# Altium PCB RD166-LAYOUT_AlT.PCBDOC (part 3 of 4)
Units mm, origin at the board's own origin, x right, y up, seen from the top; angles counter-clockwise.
Board outline 88.7 x 59.07 mm, 2 copper layers (TOP, BOTTOM), stack 0 mm thick; 138 components, 120 nets, 706 pads, 0 vias.
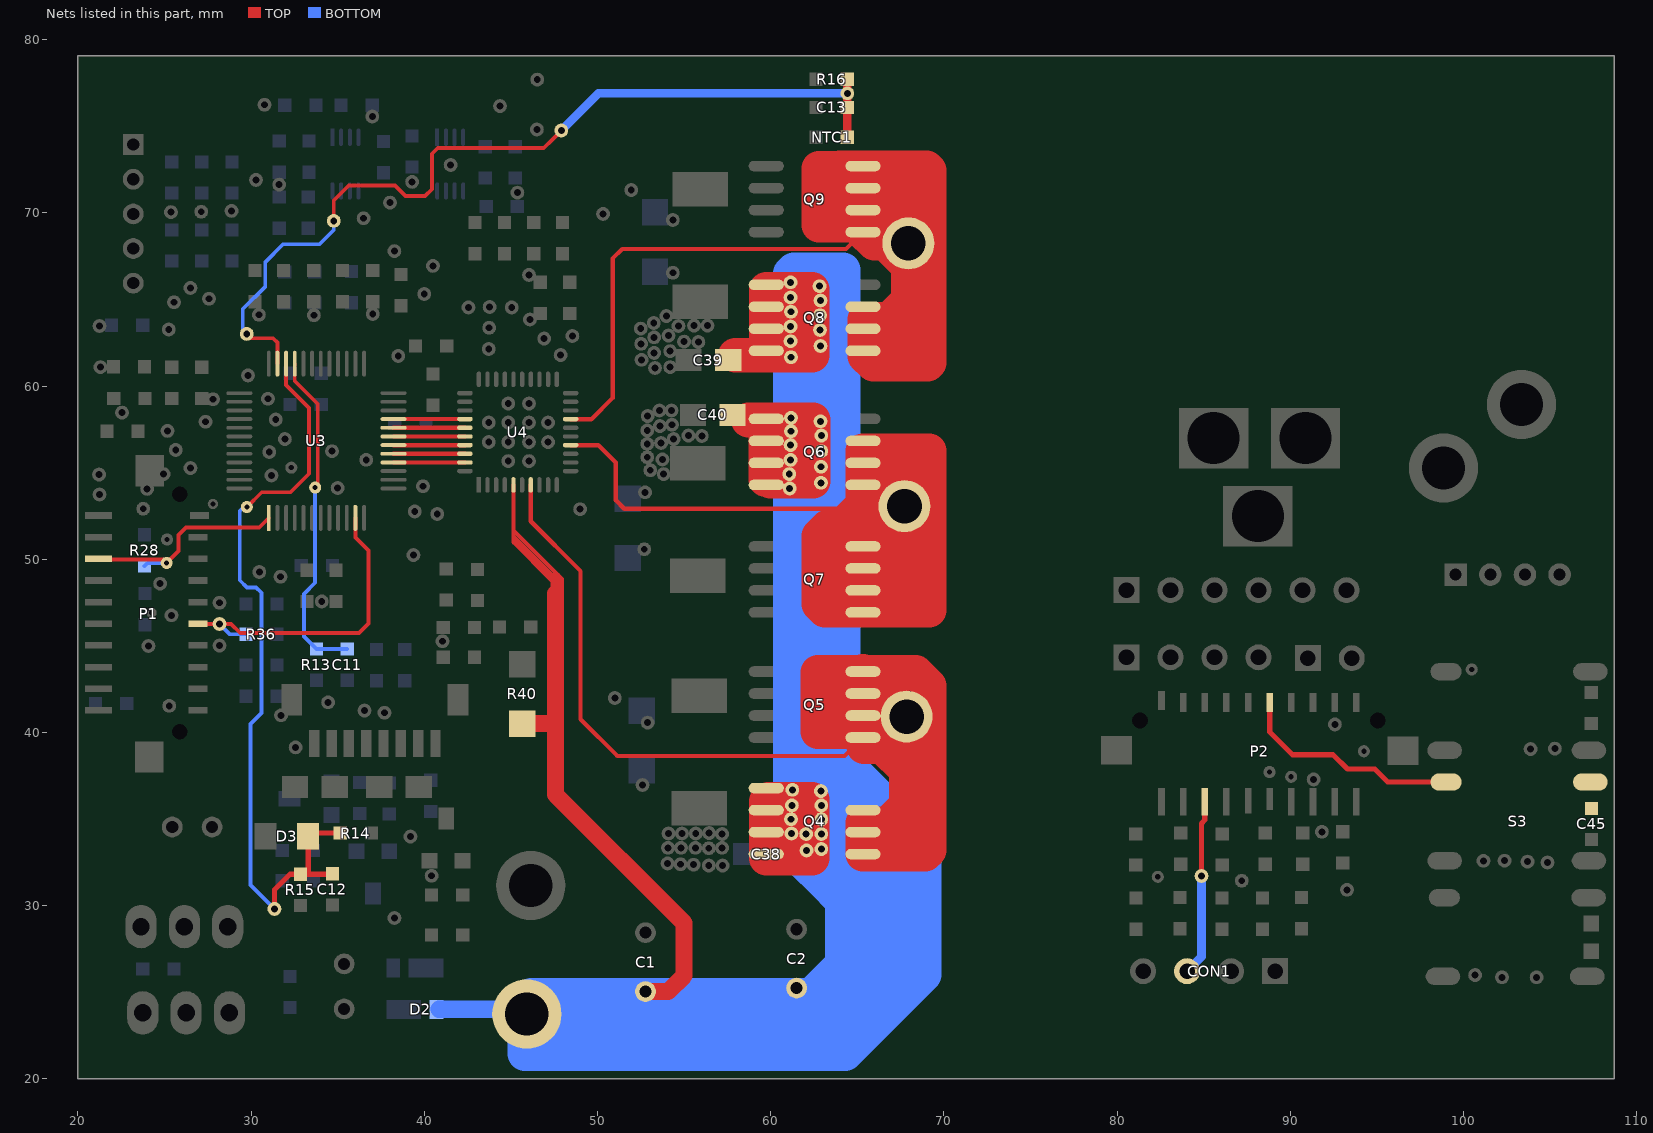
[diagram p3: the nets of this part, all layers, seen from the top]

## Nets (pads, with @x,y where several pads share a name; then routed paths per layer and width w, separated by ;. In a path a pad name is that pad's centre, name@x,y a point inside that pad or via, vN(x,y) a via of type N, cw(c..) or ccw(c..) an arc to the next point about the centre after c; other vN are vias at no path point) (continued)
TMOS: C13.1 NTC1.2 pad.@29.75,63.016 pad.@34.775,69.541 pad.@47.912,74.753 pad.@64.425,76.903 R16.2 U3.35 | length 51.7
  TOP w0.22: pad.@29.75,63.016 30.001,62.765 31.276,62.765 31.526,62.515 U3.35@31.526,61.292 ; pad.@34.776,69.542 34.776,70.715 35.645,71.584 38.307,71.584 38.926,70.965 40.051,70.965 40.451,71.365 40.451,73.415 40.776,73.74 46.901,73.74 47.402,74.241 47.402,74.242 pad.@47.912,74.753
  TOP w0.5: NTC1.2@64.425,74.366 64.425,75.331 64.426,75.332 ; 64.425,75.333 C13.1@64.425,76.091 pad.@64.425,76.903 R16.2@64.425,77.716
  BOTTOM w0.22: pad.@29.75,63.016 29.525,63.241 29.525,64.441 30.825,65.741 30.825,67.166 31.85,68.191 33.95,68.191 34.775,69.016 pad.@34.775,69.541
  BOTTOM w0.5: pad.@47.912,74.753 50.063,76.903 pad.@64.425,76.903
TXD: P1.8 pad.@25.126,49.79 R28.2 U3.1 | length 12.9
  TOP w0.22: P1.8@21.187,50.026 21.223,49.99 24.926,49.99 pad.@25.126,49.79 25.811,50.475 25.811,51.4 26.251,51.84 30.476,51.84 30.689,52.054 30.689,52.055 U3.1@31.025,52.391
  BOTTOM w0.22: R28.2@23.85,49.616 24.024,49.79 pad.@25.126,49.79
TXD1: CON1.3 P2.8 pad.@84.875,31.716 | length 10.2
  TOP w0.3: pad.@84.875,31.716 84.875,32.393 ; 84.876,32.394 84.876,34.749 85.065,34.938 P2.8@85.065,36.003
  BOTTOM w0.5: CON1.3@84.045,26.216 84.875,27.046 pad.@84.875,31.716
U: pad.@67.85,40.916 Q4.1 Q4.2 Q4.3 Q5.5 Q5.6 Q5.7 Q5.8 U4.7 | length 88.3
  TOP w0.25: U4.7@46.151,54.29 46.151,52.19 49.026,49.315 49.026,40.765 51.151,38.64 64.264,38.64 Q5.5@65.331,39.709
  TOP w2: Q5.5@65.332,39.709 Q5.5@65.376,39.709 ; Q5.6@65.332,40.979 Q5.6@65.376,40.979 ; Q5.7@65.332,42.249 Q5.7@65.376,42.249 ; Q5.8@65.332,43.519 Q5.8@65.332,43.474 ; pad.@67.851,40.915 67.826,40.89 67.826,37.815 ; 63.976,43.474 Q5.8@65.332,43.474 ; 63.976,43.474 63.976,40.958 64.643,40.291 64.885,40.049 ; 63.976,43.474 62.735,43.474 62.735,40.049 64.885,40.049 ; 64.885,40.049 64.938,40.102 65.376,40.54 ; Q5.8@65.332,43.474 Q5.8@65.376,43.474 ; Q5.5@65.376,39.709 65.376,39.19 66.451,39.19 ; Q5.5@65.376,39.709 65.376,40.54 ; 65.376,40.54 Q5.6@65.376,40.979 ; Q5.6@65.376,40.979 Q5.7@65.376,42.249 ; Q5.7@65.376,42.249 Q5.8@65.376,43.474 ; Q5.8@65.376,43.474 67.026,43.474 ; 66.451,39.19 67.826,37.815 ; 66.451,39.19 67.026,39.765 67.026,43.474 ; 67.026,43.474 68.367,43.474 69.147,42.694 69.147,35.061 ; 67.826,37.815 67.826,35.79 66.776,34.74 65.363,34.74 65.332,34.771 Q4.2@65.331,34.248 Q4.1@65.331,32.978 68.934,32.977 69.147,33.19 69.147,34.186 ; 69.147,34.186 68.088,33.127 68.088,34.002 69.147,35.061 ; 69.147,34.186 69.147,35.061
U0: U3.21 U4.34 | length 4.1
  TOP w0.22: U3.21@38.225,58.091 41.662,58.09 ; 41.663,58.091 U4.34@42.35,58.091
U2-11: P1.15 pad.@28.18,46.265 R36.1 U3.11 | length 18.5
  TOP w0.22: P1.15@26.925,46.276 26.936,46.265 pad.@28.18,46.265 28.851,46.265 29.376,45.74 36.226,45.74 36.776,46.29 36.776,50.515 36.026,51.265 U3.11@36.025,52.391
  BOTTOM w0.22: pad.@28.18,46.265 28.78,45.666 R36.1@29.7,45.666
U2-11A: C45.1 P2.15 S3.1 S3.4 | length 13.1
  TOP w0.3: P2.15@88.815,41.741 88.815,40.026 90.126,38.715 92.476,38.715 93.301,37.89 94.876,37.89 95.631,37.135 S3.1@98.996,37.135
V: pad.@67.725,53.066 Q6.1 Q6.2 Q6.3 Q7.5 Q7.6 Q7.7 Q7.8 U4.14 | length 69
  TOP w0.25: U4.14@48.45,56.591 50.051,56.59 51.051,55.59 51.051,53.415 51.551,52.915 64.151,52.915 64.626,52.44 65.326,51.74
  TOP w2: 64.151,50.565 64.151,47.065 ; Q7.6@65.331,48.201 Q7.6@65.326,48.201 ; Q7.7@65.331,49.471 Q7.7@65.326,49.471 ; Q7.8@65.331,50.741 Q7.8@65.326,50.741 ; Q6.1@65.331,54.291 Q6.1@65.326,54.291 ; Q6.2@65.331,55.561 Q6.2@65.326,55.561 ; 67.276,55.965 67.276,54.291 pad.@67.276,53.065 ; pad.@67.726,53.065 pad.@67.276,53.065 ; 64.151,47.065 Q7.5@65.326,47.065 ; 64.151,47.065 63.126,47.065 62.776,47.415 62.776,51.34 63.301,51.865 64.051,51.865 64.129,51.943 64.626,52.44 65.326,53.14 ; Q7.5@65.326,47.065 67.276,47.065 ; Q7.5@65.326,47.065 Q7.6@65.326,48.201 ; Q7.6@65.326,48.201 Q7.7@65.326,49.471 ; Q7.7@65.326,49.471 Q7.8@65.326,50.741 ; Q7.8@65.326,50.741 65.326,51.74 65.326,53.14 ; 65.326,53.14 Q6.1@65.326,54.291 ; Q6.1@65.326,54.291 Q6.2@65.326,55.561 ; Q6.2@65.326,55.561 65.326,56.265 69.147,56.265 69.147,47.065 67.276,47.065 ; 67.276,47.065 67.276,50.741 pad.@67.276,53.065
V0: U3.19 U4.36 | length 4.1
  TOP w0.22: U3.19@38.226,57.09 41.449,57.09 ; 41.45,57.091 U4.36@42.35,57.091
VDC_AD: C12.1 D3.1 pad.@29.758,53.015 pad.@31.351,29.815 R14.1 R15.2 U3.34 | length 45.4
  TOP w0.22: pad.@29.758,53.015 30.614,53.87 32.281,53.87 33.351,54.94 33.351,58.74 32.026,60.065 U3.34@32.026,61.29
  TOP w0.3: pad.@31.351,29.815 31.351,30.915 32.251,31.815 R15.2@32.85,31.816 ; R15.2@32.85,31.816 33.301,31.815 ; C12.1@34.7,31.841 34.674,31.815 33.301,31.815 ; R14.1@35.149,34.19 33.449,34.19 D3.1@33.275,34.016 33.301,33.99 33.301,31.815
  BOTTOM w0.22: pad.@29.758,53.015 29.575,53.016 29.35,52.791 29.35,48.791 29.763,48.379 30.287,48.379 30.6,48.066 30.6,41.116 29.975,40.491 29.975,31.191 pad.@31.351,29.815
VM: C1.1 C2.1 C38.2 C39.1 C40.1 D2.2 pad.@45.925,23.741 pad.@61.1,54.091 pad.@61.2,34.166 pad.@61.15,55.741 pad.@61.15,56.591 pad.@61.15,62.591 pad.@61.15,63.441 pad.@61.15,65.116 pad.@61.15,65.991 pad.@61.25,36.691 pad.@61.075,54.916 pad.@61.175,34.991 pad.@61.175,57.391 pad.@61.175,58.166 pad.@61.175,61.666 pad.@61.175,64.291 pad.@61.225,35.791 pad.@62.05,34.141 pad.@62.9,36.616 pad.@62.9,54.416 pad.@62.9,55.341 pad.@62.075,33.191 pad.@62.85,63.241 pad.@62.85,64.091 pad.@62.825,65.766 pad.@62.875,57.966 pad.@62.875,62.316 pad.@62.875,64.941 pad.@62.925,33.266 pad.@62.925,34.141 pad.@62.925,34.991 pad.@62.925,35.791 pad.@62.925,56.241 pad.@62.925,57.141 Q4.5 Q4.6 Q4.7 Q4.8 Q6.5 Q6.6 Q6.7 Q6.8 Q8.5 Q8.6 Q8.7 Q8.8 R40.2 U4.5 | length 377.2
  TOP w0.25: 45.15,52.491 U4.5@45.15,54.291 ; 45.151,52.49 45.151,51.665 ; 47.363,48.778 45.151,50.99 45.151,51.315 ; 47.401,47.59 47.401,49.065 45.151,51.315 ; 47.551,48.165 47.551,49.265 ; 47.701,47.69 47.701,49.115 ; 47.951,47.415 47.951,48.865 47.701,49.115 ; 45.151,51.315 45.151,51.665 ; 45.151,51.665 47.551,49.265 ; 47.551,49.265 47.701,49.115
  TOP w1: R40.2@45.65,40.515 47.451,40.515 ; 47.576,48.015 47.576,36.415 55.001,28.99 55.001,25.965 54.076,25.04 C1.1@52.776,25.04
  TOP w2: C39.1@57.949,61.78 Q8.8@59.998,61.78 ; 58.701,58.04 62.451,58.04 62.451,57.665 ; Q6.8@59.726,54.59 Q6.7@59.726,55.561 ; Q6.7@59.743,55.561 Q6.7@59.726,55.561 ; Q6.6@59.743,56.831 Q6.6@59.726,56.831 ; Q6.8@59.969,54.515 61.076,54.515 ; pad.@61.014,61.907 pad.@61.014,62.59 ; pad.@61.141,34.991 pad.@61.141,35.79 ; pad.@61.141,36.025 pad.@61.141,35.79 ; pad.@61.15,55.741 pad.@61.076,55.74 ; pad.@61.15,56.591 pad.@61.076,56.59 ; pad.@61.15,62.591 pad.@61.014,62.59 ; pad.@61.151,63.44 pad.@61.014,63.44 ; pad.@61.15,65.116 pad.@61.014,65.115 ; pad.@61.175,34.991 61.141,34.99 61.141,34.248 pad.@61.141,34.165 ; pad.@61.175,57.391 61.173,57.385 61.076,57.19 pad.@61.076,56.59 ; pad.@61.175,64.291 pad.@61.014,64.29 ; pad.@61.201,34.165 pad.@61.141,34.165 ; pad.@61.226,35.79 pad.@61.141,35.79 ; pad.@62.05,34.141 pad.@62.411,34.14 ; pad.@62.075,33.191 pad.@62.411,33.19 ; Q6.7@59.726,55.561 Q6.6@59.726,56.831 ; Q6.6@59.726,56.831 59.726,57.665 62.451,57.665 ; Q8.8@59.998,61.78 62.411,61.78 62.411,63.241 62.411,64.941 62.411,65.583 61.014,65.583 ; Q8.8@59.998,61.78 Q8.8@59.743,62.035 Q8.7@59.743,63.305 59.744,65.583 61.014,65.583 ; pad.@61.014,62.59 61.014,63.305 pad.@61.014,63.44 ; pad.@61.014,63.44 pad.@61.014,64.29 ; pad.@61.014,64.29 pad.@61.014,65.115 ; pad.@61.014,65.115 61.014,65.583 ; 61.076,54.515 62.451,54.515 62.451,56.241 62.451,57.665 ; 61.076,54.515 61.076,55.561 pad.@61.076,55.74 ; pad.@61.076,55.74 pad.@61.076,56.59 ; 61.141,32.74 62.411,32.74 pad.@62.411,33.19 ; 61.141,32.74 61.141,34.141 pad.@61.141,34.165 ; 61.141,32.74 59.744,32.74 59.744,36.025 59.871,36.152 62.411,36.152 62.411,34.166 pad.@62.411,34.14 ; pad.@62.411,33.191 pad.@62.411,34.14
  BOTTOM w1: D2.2@40.852,24.016 pad.@45.375,24.016 ; pad.@45.375,24.016 45.8,23.803 pad.@45.925,23.741 45.8,23.866 45.65,24.016 pad.@45.375,24.016
  BOTTOM w2: pad.@45.925,23.741 pad.@45.8,23.741 ; pad.@61.075,54.916 pad.@61.14,54.916 ; pad.@61.1,54.091 pad.@61.14,54.091 ; 62.202,66.266 62.202,65.991 ; 63.55,39.016 64.188,38.378 ; 64.188,31.379 64.188,33.366 ; pad.@45.8,23.741 45.8,23.803 45.8,23.866 pad.@45.8,24.441 ; pad.@45.8,23.741 45.8,21.466 64.3,21.466 67.7,24.866 ; pad.@45.8,24.441 46.212,24.028 47.3,22.941 63.125,22.941 65.875,25.691 65.875,31.679 64.188,33.366 ; pad.@45.8,24.441 46.175,24.816 62.35,24.816 64.15,26.616 64.15,30.266 62.925,31.491 ; C38.2@61.14,33.366 pad.@62.05,33.366 ; C38.2@61.14,33.366 pad.@61.14,34.166 ; C38.2@61.14,33.366 61.14,33.276 61.162,33.254 61.65,32.766 62.038,32.378 62.925,31.491 ; pad.@61.14,34.166 pad.@61.14,34.991 ; pad.@61.14,34.166 pad.@61.2,34.166 62.075,34.166 pad.@62.202,34.166 ; pad.@61.14,34.991 pad.@61.14,35.791 ; pad.@61.14,34.991 pad.@61.175,34.991 62.202,34.991 ; pad.@61.14,35.791 pad.@61.14,36.691 ; pad.@61.14,35.791 pad.@61.225,35.791 62.202,35.791 ; pad.@61.14,36.691 pad.@61.25,36.691 62.202,36.691 ; pad.@61.14,36.691 pad.@61.14,54.091 ; pad.@61.14,54.091 pad.@61.14,54.916 ; pad.@61.14,54.091 62.202,54.091 ; pad.@61.14,54.916 62.202,54.916 ; pad.@61.14,54.916 pad.@61.14,55.741 ; pad.@61.14,55.741 pad.@61.15,55.741 62.202,55.741 ; pad.@61.14,55.741 pad.@61.14,56.591 ; pad.@61.14,56.591 pad.@61.15,56.591 62.202,56.591 ; pad.@61.14,56.591 pad.@61.14,57.391 ; pad.@61.14,57.391 pad.@61.175,57.391 62.202,57.391 ; pad.@61.14,57.391 pad.@61.14,58.166 ; pad.@61.14,58.166 pad.@61.175,58.166 62.202,58.166 ; pad.@61.14,58.166 pad.@61.14,61.666 ; pad.@61.14,61.666 pad.@61.175,61.666 62.202,61.666 ; pad.@61.14,61.666 pad.@61.14,62.591 ; pad.@61.14,62.591 pad.@61.14,63.441 ; pad.@61.14,62.591 pad.@61.15,62.591 62.202,62.591 ; pad.@61.14,63.441 pad.@61.14,64.291 ; pad.@61.14,63.441 pad.@61.15,63.441 62.202,63.441 ; pad.@61.14,64.291 pad.@61.14,65.116 ; pad.@61.14,64.291 pad.@61.175,64.291 62.202,64.291 ; pad.@61.14,65.116 pad.@61.15,65.116 62.202,65.116 ; pad.@61.14,65.116 pad.@61.14,65.991 ; pad.@61.14,65.991 pad.@61.15,65.991 62.202,65.991 ; pad.@61.14,65.991 61.14,66.516 61.327,66.703 62.825,66.703 ; pad.@62.05,33.366 pad.@62.05,34.141 pad.@62.202,34.141 ; pad.@62.05,33.366 pad.@62.075,33.366 ; pad.@62.075,33.366 pad.@62.678,33.366 ; pad.@62.075,33.366 pad.@62.075,33.191 62.306,33.258 pad.@62.678,33.366 ; pad.@62.202,34.141 pad.@62.925,34.141 pad.@62.925,33.366 ; pad.@62.202,34.141 pad.@62.202,34.166 ; pad.@62.202,34.141 62.202,34.064 62.525,33.741 62.575,33.691 pad.@62.85,33.416 ; pad.@62.202,34.166 62.202,34.991 ; 62.202,34.991 pad.@62.925,34.991 64.188,34.991 ; 62.202,34.991 62.202,35.791 ; 62.202,35.791 pad.@62.925,35.791 64.188,35.791 ; 62.202,35.791 62.202,36.616 ; 62.202,36.616 62.202,36.691 ; 62.202,36.616 pad.@62.9,36.616 64.188,36.616 ; 62.202,36.691 62.202,54.091 ; 62.202,54.091 62.202,54.416 ; 62.202,54.416 62.202,54.916 ; 62.202,54.416 pad.@62.9,54.416 64.188,54.416 ; 62.202,54.916 62.202,55.341 ; 62.202,55.341 pad.@62.9,55.341 64.188,55.341 ; 62.202,55.341 62.202,55.741 ; 62.202,55.741 62.202,56.241 ; 62.202,56.241 pad.@62.925,56.241 64.188,56.241 ; 62.202,56.241 62.202,56.591 ; 62.202,56.591 62.202,57.141 ; 62.202,57.141 pad.@62.925,57.141 64.188,57.141 ; 62.202,57.141 62.202,57.391 ; 62.202,57.391 62.202,57.966 ; 62.202,57.966 62.202,58.166 ; 62.202,57.966 pad.@62.875,57.966 64.188,57.966 ; 62.202,58.166 62.202,61.666 ; 62.202,61.666 62.202,62.316 ; 62.202,62.316 pad.@62.875,62.316 64.188,62.316 ; 62.202,62.316 62.202,62.591 ; 62.202,62.591 62.202,63.241 ; 62.202,63.241 pad.@62.85,63.241 64.188,63.241 ; 62.202,63.241 62.202,63.441 ; 62.202,63.441 62.202,64.091 ; 62.202,64.091 pad.@62.85,64.091 64.188,64.091 ; 62.202,64.091 62.202,64.291 ; 62.202,64.291 62.202,64.941 ; 62.202,64.941 pad.@62.875,64.941 64.188,64.941 ; 62.202,64.941 62.202,65.116 ; 62.202,65.116 62.202,65.766 ; 62.202,65.766 62.202,65.991 ; 62.202,65.766 pad.@62.825,65.766 62.825,66.703 ; pad.@62.678,33.366 pad.@62.875,33.366 ; pad.@62.678,33.366 pad.@62.85,33.416 ; 62.825,66.703 64.188,66.703 64.188,64.941 ; pad.@62.85,33.416 pad.@62.875,33.366 ; pad.@62.875,33.366 pad.@62.925,33.366 ; pad.@62.875,33.366 pad.@62.925,33.266 62.925,31.491 ; pad.@62.925,33.366 64.188,33.366 ; 64.188,33.366 64.188,34.991 ; 64.188,34.991 64.188,35.791 ; 64.188,35.791 64.188,35.953 ; 64.188,35.953 64.188,36.616 ; 64.188,35.953 67.7,32.441 67.7,24.866 ; 64.188,36.616 64.188,38.378 ; 64.188,38.378 64.188,54.416 ; 64.188,38.378 68.85,33.716 68.85,26.016 67.7,24.866 ; 64.188,54.416 64.188,55.341 ; 64.188,55.341 64.188,56.241 ; 64.188,56.241 64.188,57.141 ; 64.188,57.141 64.188,57.966 ; 64.188,57.966 64.188,62.316 ; 64.188,62.316 64.188,63.241 ; 64.188,63.241 64.188,64.091 ; 64.188,64.091 64.188,64.941
VSP: C11.1 pad.@33.701,54.14 R13.2 U3.33 | length 19.4
  TOP w0.22: U3.33@32.525,61.291 32.526,60.29 33.851,58.965 33.851,54.29 pad.@33.701,54.14
  BOTTOM w0.22: pad.@33.701,54.14 33.7,48.641 33.05,47.991 33.05,45.541 R13.2@33.775,44.816 C11.1@35.55,44.816
W: pad.@67.95,68.241 Q8.1 Q8.2 Q8.3 Q9.5 Q9.6 Q9.7 Q9.8 U4.17 | length 92.4
  TOP w0.25: U4.17@48.451,58.09 49.651,58.09 50.876,59.315 50.876,67.365 51.426,67.915 64.355,67.915 Q9.5@65.331,68.893
  TOP w2: 64.001,69.303 64.001,72.577 ; 64.001,69.303 64.921,69.303 Q9.5@65.331,68.893 ; 64.001,69.303 62.789,69.303 62.789,72.577 64.001,72.577 ; 64.001,72.577 64.001,72.59 Q9.8@65.332,72.59 ; Q9.5@65.331,68.893 Q9.6@65.331,70.163 Q9.8@65.332,72.59 ; Q9.5@65.331,68.893 65.984,68.24 pad.@66.626,68.24 ; Q9.8@65.332,72.59 66.751,72.59 ; pad.@66.626,68.24 pad.@67.951,68.24 ; pad.@66.626,68.24 67.288,67.579 pad.@67.951,66.915 ; 66.751,72.59 66.876,72.465 66.876,69.315 pad.@67.951,68.24 ; 66.751,72.59 68.326,72.59 ; 66.851,63.865 65.451,63.865 65.451,61.74 65.926,61.265 66.901,61.265 ; 66.851,63.865 66.901,63.815 66.901,61.265 ; 66.851,63.865 67.951,64.965 pad.@67.951,66.915 ; 66.901,61.265 68.326,61.265 ; pad.@67.951,66.915 pad.@67.951,68.24 ; 68.326,61.265 68.326,72.59 ; 68.326,61.265 69.072,61.265 69.147,61.34 69.147,72.444 69.001,72.59 68.326,72.59
W0: U3.17 U4.38 | length 4.1
  TOP w0.25: U3.17@38.225,56.091 41.622,56.09 ; 41.622,56.091 U4.38@42.35,56.091
X0: U3.20 U4.35 | length 4.1
  TOP w0.25: U3.20@38.226,57.59 41.622,57.59 ; 41.622,57.591 U4.35@42.35,57.591
Y0: U3.18 U4.37 | length 4.1
  TOP w0.25: U3.18@38.225,56.591 41.521,56.59 ; 41.522,56.591 U4.37@42.35,56.591
Z0: U3.16 U4.39 | length 4.1
  TOP w0.25: U3.16@38.225,55.591 U4.39@42.35,55.591
pads on no net: P1.23 P1.24 P2.21 P2.23 P2.24 SW1.6 SW1.9

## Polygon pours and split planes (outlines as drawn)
+5V1 on TOP "TOP171" (solid, pour order 295): 37 vertices, not listed, extent 79.076,25.415 94.651,49.19
19VDC on TOP "TOP169" (solid, pour order 293): 105.301,60.74 105.901,60.14 105.901,57.99 104.776,56.865 102.426,56.865 101.176,58.115 95.801,58.115 92.976,55.29 88.851,55.29 88.851,58.715 90.876,60.74
EMG1 on TOP "TOP131" (solid, pour order 255): 93.946,43.154 cw(c93.801,43.191) 93.695,43.085 93.02,43.761 93.542,44.328 94.119,43.829 93.946,43.154
GND1 on TOP "TOP121" (solid, pour order 245): 98.151,39.64 106.251,39.64 106.526,39.915 106.526,40.84 106.701,41.015 108.026,41.015 108.226,40.815 108.226,38.54 108.126,38.44 97.976,38.44 97.851,38.565 97.851,39.34
GND1 on TOP "TOP120" (solid, pour order 244): 106.676,34.315 108.076,34.315 108.376,34.015 108.376,32.165 108.101,31.89 98.026,31.89 97.726,32.19 97.726,32.765 98.101,33.14 106.301,33.14 106.651,33.49 106.651,34.29
GND1 on TOP "TOP119" (solid, pour order 243): 90.319,33.665 cw(c90.319,33.838) 90.216,33.7 90.201,33.715 90.176,33.74 cw(c90.368,33.841) 90.151,33.841 90.151,34.541 cw(c90.286,34.53) 90.286,34.665 93.387,34.665 cw(c93.386,34.575) 93.476,34.575 93.476,33.811 cw(c93.33,33.811) 93.336,33.665
GND1 on TOP "TOP118" (solid, pour order 242): 27 vertices, not listed, extent 79.176,24.715 98.851,27.065
GND1 on TOP "TOP117" (solid, pour order 241): 108.376,25.69 108.001,25.315 98.051,25.315 97.776,25.59 97.726,25.64 97.726,26.44 97.951,26.665 106.276,26.665 106.751,27.14 106.751,27.765 108.176,27.765 108.376,27.565
GND1 on TOP "TOP116" (solid, pour order 240): 82.245,32.054 cw(c82.351,31.948) 82.457,32.054 ccw(c82.697,32.153) 82.598,31.913 82.351,31.628 82.103,31.913 ccw(c82.004,32.153) 82.245,32.054
GND1 on TOP "TOP115" (solid, pour order 239): 87.051,44.815 84.776,47.09 84.776,49.006 cw(c84.946,48.994) 84.946,49.165 86.476,49.165 86.876,48.765 86.876,47.24 87.576,46.54 88.601,45.515 91.401,45.515 91.801,45.115 91.801,43.615 91.651,43.465 87.526,43.465 87.051,43.94
K-UP1 on TOP "TOP107" (solid, pour order 231): 106.301,31.09 108.226,31.09 108.401,30.915 108.401,28.865 108.101,28.565 106.851,28.565 106.551,28.865 106.551,29.64 106.251,29.94 98.101,29.94 97.851,30.19 97.851,30.815 98.201,31.165
LEDB on TOP "TOP105" (solid, pour order 229): 89.199,33.791 89.049,33.641 87.974,33.641 87.974,33.666 87.674,33.966 87.674,35.1 cw(c87.715,35.095) 87.715,35.136 87.956,35.136 87.956,35.311 cw(c87.992,35.301) 87.992,35.338 88.424,35.338 88.424,35.315 88.575,35.315 89.199,34.691
N172117 on TOP "TOP100" (solid, pour order 224): 91.226,32.84 91.401,32.665 91.401,30.315 91.101,30.015 90.301,30.015 90.226,30.09 90.226,32.84
N29992 on TOP "TOP89" (solid, pour order 213): 84.126,32.74 84.126,30.015 83.226,30.015 83.176,30.065 83.176,32.815 84.051,32.815
N30008 on TOP "TOP88" (solid, pour order 212): 86.526,32.715 86.526,30.065 86.451,29.99 85.676,29.99 85.601,30.065 85.601,32.715
N30012 on TOP "TOP87" (solid, pour order 211): 89.151,32.69 89.151,30.09 89.001,29.94 88.026,29.94 87.951,30.015 87.951,32.84 89.001,32.84
N30064 on TOP "TOP86" (solid, pour order 210): 81.626,32.69 81.626,30.04 81.501,29.915 80.751,29.915 80.576,30.09 80.576,32.661 cw(c80.721,32.644) 80.721,32.79 81.526,32.79
NRESET1 on TOP "TOP63" (solid, pour order 187): 108.426,41.99 108.151,41.715 106.676,41.715 106.551,41.84 106.551,42.865 106.276,43.14 98.101,43.14 97.926,43.315 97.926,43.94 98.126,44.14 108.201,44.14 108.426,43.915
NRESET1 on TOP "TOP62" (solid, pour order 186): 93.9,39.116 cw(c94.05,39.116) 94.05,39.266 94.25,39.266 94.276,38.889 93.9,38.916 93.9,39.116
PGND1 on TOP "TOP46" (solid, pour order 170): 86.251,54.215 93.226,54.215 96.326,57.315 100.426,57.315 101.201,56.54 101.201,53.615 100.051,52.465 97.701,52.465 95.876,50.64 85.976,50.64 85.976,53.94
SCL1 on TOP "TOP42" (solid, pour order 166): 99.642,47.847 cw(c99.551,47.965) 99.459,47.847 ccw(c98.424,47.474) 98.9,48.466 99.55,49.154 100.2,48.466 ccw(c100.677,47.476) 99.642,47.847
SCLK1 on TOP "TOP39" (solid, pour order 163): 88.907,37.326 cw(c88.801,37.432) 88.695,37.326 88.554,37.468 88.801,37.753 89.048,37.468 88.907,37.326
SDA1 on TOP "TOP38" (solid, pour order 162): 92.453,40.929 cw(c92.565,40.83) 92.671,40.936 92.858,40.749 92.576,40.428 92.286,40.743 92.453,40.929
SWCLK1 on TOP "TOP33" (solid, pour order 157): 85.025,43.591 cw(c85.025,43.741) 84.875,43.741 84.875,44.341 85.652,44.368 85.625,43.591 85.025,43.591
SYNC2A on TOP "TOP30" (solid, pour order 154): 91.432,36.806 cw(c91.326,36.912) 91.206,36.822 91.054,37.023 91.353,37.328 91.634,37.008 91.432,36.806
TXD1 on TOP "TOP20" (solid, pour order 144): 84.769,32.176 cw(c84.875,32.07) 84.981,32.176 ccw(c85.282,32.3) 85.158,31.999 84.875,31.678 84.592,31.999 ccw(c84.468,32.3) 84.769,32.176
U2-11A on TOP "TOP16" (solid, pour order 140): 98.036,37.615 108.176,37.615 108.376,37.415 108.376,35.64 107.901,35.165 106.876,35.165 106.601,35.44 106.601,36.015 106.051,36.565 97.926,36.565 97.901,36.59 97.901,37.465 98.026,37.59
+5V on TOP "TOP176" (solid, pour order 300): 32.494,50.118 32.494,49.451 31.928,48.886 31.674,48.886 31.619,48.941 31.619,49.463 32.314,50.157 32.454,50.157
+5V on TOP "TOP175" (solid, pour order 299): 27.501,27.79 27.501,33.726 cw(c27.602,33.725) 27.621,33.825 ccw(c27.75,34.541) 28.477,34.53 28.478,34.58 29.66,34.58 30.07,34.171 30.276,33.965 30.276,33.127 30.276,28.065 29.451,27.24 28.051,27.24
+5V on TOP "TOP174" (solid, pour order 298): 17 vertices, not listed, extent 20.751,33.115 31.426,41.668
+5V on TOP "TOP173" (solid, pour order 297): 29.3,39.614 31.351,41.665 31.351,42.461 cw(c31.441,42.45) 31.441,42.54 32.92,42.54 cw(c32.917,42.457) 33.001,42.457 33.001,40.79 32.876,40.665 31.78,40.665 31.426,40.311 31.026,39.911 31.026,38.915 29.998,38.915
+5V on TOP "TOP172" (solid, pour order 296): 22.976,58.215 22.251,57.49 22.251,57.24 21.976,56.965 21.176,56.965 21.176,59.165 21.701,59.69 22.401,59.69 22.401,59.29 22.976,58.715
12V on TOP "TOP170" (solid, pour order 294): 24.051,22.115 22.626,22.115 21.901,22.84 21.901,29.665 22.276,30.04 24.076,30.04 24.176,29.94 24.226,29.94 24.526,29.64 24.526,22.59
5V on TOP "TOP168" (solid, pour order 292): 27.332,59.032 cw(c27.347,59.094) 27.302,59.139 ccw(c27.152,59.505) 27.517,59.354 27.815,59.246 27.547,58.982 ccw(c27.379,58.749) 27.332,59.032
5V on TOP "TOP167" (solid, pour order 291): 46.245,63.323 cw(c46.151,63.38) 46.073,63.302 ccw(c45.638,63.123) 45.817,63.558 46.097,63.868 46.399,63.579 ccw(c46.629,63.266) 46.245,63.323
5V on TOP "TOP166" (solid, pour order 290): 47.645,64.129 cw(c47.938,64.191) 47.645,64.253 ccw(c47.349,64.98) 48.019,64.572 48.475,64.191 48.019,63.81 ccw(c47.349,63.402) 47.645,64.129
5V on TOP "TOP165" (solid, pour order 289): 47.455,64.253 cw(c47.162,64.191) 47.455,64.129 ccw(c47.751,63.402) 47.081,63.81 46.625,64.191 47.081,64.572 ccw(c47.751,64.98) 47.455,64.253
AGND on TOP "TOP164" (solid, pour order 288): 27.873,61.125 cw(c27.575,61.091) 27.873,61.056 ccw(c28.23,60.362) 27.531,60.71 27.075,61.091 27.531,61.472 ccw(c28.23,61.82) 27.873,61.125
AGND on TOP "TOP163" (solid, pour order 287): 26.394,61.029 cw(c26.688,61.091) 26.394,61.154 ccw(c26.1,61.879) 26.769,61.472 27.225,61.091 26.769,60.71 ccw(c26.099,60.302) 26.394,61.029
AGND on TOP "TOP162" (solid, pour order 286): 26.18,61.153 cw(c25.887,61.091) 26.18,61.029 ccw(c26.476,60.302) 25.806,60.71 25.35,61.091 25.806,61.472 ccw(c26.476,61.88) 26.18,61.153
AGND on TOP "TOP161" (solid, pour order 285): 24.648,61.04 cw(c24.938,61.116) 24.65,61.202 ccw(c24.43,61.944) 25.044,61.472 25.5,61.087 25.044,60.71 ccw(c24.359,60.29) 24.648,61.04
AGND on TOP "TOP160" (solid, pour order 284): 24.605,61.178 cw(c24.312,61.116) 24.605,61.054 ccw(c24.901,60.327) 24.231,60.735 23.775,61.116 24.231,61.497 ccw(c24.901,61.905) 24.605,61.178
AGND on TOP "TOP159" (solid, pour order 283): 30.98,66.728 cw(c30.687,66.666) 30.98,66.603 ccw(c31.276,65.877) 30.606,66.285 30.15,66.666 30.606,67.047 ccw(c31.276,67.455) 30.98,66.728
AGND on TOP "TOP158" (solid, pour order 282): 29.469,66.603 cw(c29.763,66.665) 29.469,66.728 ccw(c29.174,67.455) 29.844,67.047 30.3,66.666 29.844,66.285 ccw(c29.175,65.876) 29.469,66.603
AGND on TOP "TOP157" (solid, pour order 281): 32.63,66.728 cw(c32.337,66.666) 32.63,66.604 ccw(c32.926,65.877) 32.256,66.285 31.8,66.666 32.256,67.047 ccw(c32.926,67.455) 32.63,66.728
AGND on TOP "TOP156" (solid, pour order 280): 31.119,66.603 cw(c31.413,66.666) 31.119,66.728 ccw(c30.824,67.455) 31.494,67.047 31.95,66.666 31.494,66.285 ccw(c30.825,65.877) 31.119,66.603
AGND on TOP "TOP155" (solid, pour order 279): 34.38,66.728 cw(c34.087,66.666) 34.38,66.603 ccw(c34.676,65.877) 34.006,66.285 33.55,66.666 34.006,67.047 ccw(c34.676,67.455) 34.38,66.728
AGND on TOP "TOP154" (solid, pour order 278): 32.869,66.603 cw(c33.163,66.666) 32.869,66.729 ccw(c32.575,67.454) 33.244,67.047 33.7,66.666 33.244,66.285 ccw(c32.574,65.877) 32.869,66.603
AGND on TOP "TOP153" (solid, pour order 277): 36.03,66.728 cw(c35.737,66.666) 36.03,66.604 ccw(c36.326,65.877) 35.656,66.285 35.2,66.666 35.656,67.047 ccw(c36.326,67.455) 36.03,66.728
AGND on TOP "TOP152" (solid, pour order 276): 34.519,66.603 cw(c34.813,66.666) 34.519,66.728 ccw(c34.224,67.455) 34.894,67.047 35.35,66.666 34.894,66.285 ccw(c34.225,65.877) 34.519,66.603
AGND on TOP "TOP151" (solid, pour order 275): 37.748,66.7 cw(c37.45,66.666) 37.748,66.631 ccw(c38.106,65.936) 37.406,66.285 36.95,66.666 37.406,67.047 ccw(c38.106,67.396) 37.748,66.7
AGND on TOP "TOP150" (solid, pour order 274): 36.269,66.603 cw(c36.563,66.666) 36.269,66.729 ccw(c35.975,67.454) 36.644,67.047 37.1,66.666 36.644,66.285 ccw(c35.974,65.877) 36.269,66.603
AGND on TOP "TOP149" (solid, pour order 273): 37.895,66.379 cw(c38.188,66.441) 37.895,66.503 ccw(c37.599,67.23) 38.269,66.822 38.725,66.441 38.269,66.06 ccw(c37.599,65.652) 37.895,66.379
AGND on TOP "TOP148" (solid, pour order 272): 39.405,66.503 cw(c39.112,66.441) 39.405,66.379 ccw(c39.701,65.652) 39.031,66.06 38.575,66.441 39.031,66.822 ccw(c39.701,67.23) 39.405,66.503
AGND on TOP "TOP147" (solid, pour order 271): 47.645,65.928 cw(c47.938,65.991) 47.645,66.053 ccw(c47.349,66.78) 48.019,66.372 48.475,65.991 48.019,65.61 ccw(c47.349,65.202) 47.645,65.928
AGND on TOP "TOP146" (solid, pour order 270): 40.078,64.828 cw(c40,64.906) 39.922,64.828 ccw(c39.573,64.684) 39.717,65.033 40,65.343 40.283,65.033 ccw(c40.427,64.684) 40.078,64.828
AMP_U on TOP "TOP145" (solid, pour order 269): 41.604,72.278 cw(c41.526,72.355) 41.448,72.277 ccw(c41.098,72.133) 41.242,72.483 41.525,72.793 41.808,72.483 ccw(c41.953,72.135) 41.604,72.278
AMP_U on TOP "TOP144" (solid, pour order 268): 40.79,67.341 cw(c40.79,67.231) 40.9,67.231 ccw(c41.247,67.086) 40.9,66.941 40.481,66.921 40.5,67.341 ccw(c40.645,67.688) 40.79,67.341
AMP_U on TOP "TOP143" (solid, pour order 267): 47.004,62.263 cw(c46.926,62.34) 46.848,62.262 ccw(c46.515,62.126) 46.652,62.458 46.925,62.769 47.198,62.459 ccw(c47.336,62.128) 47.004,62.263
AMP_V on TOP "TOP142" (solid, pour order 266): 47.261,61.5 47.551,61.79 47.901,61.802 47.876,61.39 ccw(c47.568,60.653) 47.261,61.39
AMP_V on TOP "TOP141" (solid, pour order 265): 38.198,69.852 ccw(c37.423,69.533) 37.742,70.308 38.015,70.617 38.276,70.34 38.276,69.93
AMP_V on TOP "TOP140" (solid, pour order 264): 38.198,68.28 cw(c38.276,68.202) 38.354,68.279 ccw(c38.703,68.422) 38.558,68.073 38.275,67.763 37.992,68.074 ccw(c37.848,68.424) 38.198,68.28
AMP_W on TOP "TOP139" (solid, pour order 263): 48.783,62.329 cw(c48.676,62.355) 48.598,62.278 ccw(c48.037,62.047) 48.268,62.608 48.545,62.917 48.863,62.659 ccw(c49.218,62.398) 48.783,62.329
CAL on TOP "TOP138" (solid, pour order 262): 38.969,62.293 cw(c39.077,62.316) 38.969,62.339 ccw(c38.805,62.632) 39.119,62.514 39.528,62.316 39.119,62.118 ccw(c38.805,62) 38.969,62.293
CAL on TOP "TOP137" (solid, pour order 261): 38.792,62.141 cw(c38.792,62.031) 38.902,62.03 ccw(c39.248,61.883) 38.9,61.74 38.48,61.722 38.5,62.141 ccw(c38.646,62.491) 38.792,62.141
CAL on TOP "TOP136" (solid, pour order 260): 29.535,60.216 cw(c29.535,60.326) 29.425,60.326 ccw(c29.078,60.471) 29.425,60.616 29.844,60.635 29.825,60.216 ccw(c29.68,59.869) 29.535,60.216
DIN on TOP "TOP135" (solid, pour order 259): 25.489,46.288 cw(c25.401,46.376) 25.312,46.288 25.118,46.482 25.401,46.796 25.683,46.482 25.489,46.288
EMG on TOP "TOP134" (solid, pour order 258): 40.46,52.216 cw(c40.46,52.326) 40.35,52.326 40.35,52.616 40.769,52.635 40.75,52.216 40.46,52.216
EMG on TOP "TOP133" (solid, pour order 257): 41.026,53.302 41.026,52.89 40.74,52.59 40.467,52.899 40.948,53.38
EMG on TOP "TOP132" (solid, pour order 256): 36.286,69.045 cw(c36.21,69.124) 36.1,69.124 36.1,69.691 36.512,69.715 36.576,69.321 36.286,69.045
EN on TOP "TOP130" (solid, pour order 254): 42.689,67.035 cw(c42.669,67.159) 42.59,67.062 ccw(c42.266,67.091) 42.544,67.26 42.94,67.669 43.306,67.26 ccw(c43.272,66.393) 42.689,67.035
FR1 on TOP "TOP129" (solid, pour order 253): 39.525,54.506 cw(c39.635,54.506) 39.635,54.616 ccw(c39.78,54.964) 39.925,54.616 39.944,54.196 39.525,54.216 ccw(c39.177,54.361) 39.525,54.506
GND on TOP "TOP128" (solid, pour order 252): 25.276,27.115 25.051,27.34 25.051,30.215 24.776,30.49 24.776,35.915 25.226,36.365 26.051,36.365 26.526,35.89 26.526,32.015 27.101,31.44 27.101,27.515 26.676,27.09 25.286,27.09
GND on TOP "TOP127" (solid, pour order 251): 26.276,30.665 27.101,29.84 27.101,22.715 26.626,22.24 25.426,22.24 25.051,22.615 25.051,30.161 25.772,30.161
GND on TOP "TOP126" (solid, pour order 250): 28.326,54.59 26.652,52.917 26.275,52.917 26.275,52.539 26.076,52.34 20.976,52.34 20.976,55.34 25.799,55.34 cw(c25.799,55.239) 25.901,55.243 ccw(c26.501,55.265) 26.854,54.78 28.136,54.78
GND on TOP "TOP125" (solid, pour order 249): 20.901,60.667 20.751,60.817 20.751,61.367 20.901,61.516 22.326,61.516 22.351,61.492 22.376,61.466 22.376,60.692 22.376,60.667
GND on TOP "TOP124" (solid, pour order 248): 28.22,58.064 28.033,57.877 27.381,57.877 27.301,57.957 27.301,58.124 27.607,58.43 28.179,58.43 28.22,58.389
GND on TOP "TOP123" (solid, pour order 247): 37.14,58.677 37.455,58.677 37.455,58.558 37.437,58.54 37.375,58.54 36.848,58.014 36.848,55.821 36.735,55.708 36.658,55.708 36.414,55.952 36.414,57.951
GND on TOP "TOP122" (solid, pour order 246): 30.303,54.696 30.633,55.027 31.094,55.027 31.24,54.881 31.24,54.803 30.94,54.503 30.348,54.503 30.303,54.548
HU on TOP "TOP114" (solid, pour order 238): 25.456,69.556 cw(c25.375,69.638) 25.294,69.556 ccw(c24.952,69.416) 25.092,69.758 25.375,70.07 25.658,69.758 ccw(c25.798,69.416) 25.456,69.556
HU on TOP "TOP113" (solid, pour order 237): 25.261,65.427 cw(c25.376,65.418) 25.457,65.5 ccw(c26.096,65.762) 25.833,65.124 25.558,64.814 25.234,65.051 ccw(c24.795,65.271) 25.261,65.427
HU on TOP "TOP112" (solid, pour order 236): 25.66,57.497 cw(c25.579,57.415) 25.66,57.334 ccw(c25.801,56.992) 25.459,57.132 25.147,57.415 25.459,57.698 ccw(c25.801,57.839) 25.66,57.497
HV on TOP "TOP111" (solid, pour order 235): 24.192,70.431 23.701,69.94 23.175,69.929 23.2,70.541 ccw(c23.696,71.731) 24.192,70.541
HW on TOP "TOP110" (solid, pour order 234): 28.475,69.449 28.475,70.116 28.886,70.141 28.875,69.739 28.585,69.449
K-UP on TOP "TOP109" (solid, pour order 233): 27.688,47.413 cw(c27.766,47.49) 27.688,47.568 27.893,47.773 28.203,47.49 27.893,47.208 27.688,47.413
K-UP on TOP "TOP108" (solid, pour order 232): 28.664,47.568 cw(c28.586,47.49) 28.664,47.413 28.459,47.208 28.148,47.49 28.459,47.773 28.664,47.568
LED3 on TOP "TOP106" (solid, pour order 230): 24.201,48.574 cw(c24.343,48.715) 24.33,48.915 ccw(c24.444,49.243) 24.597,48.931 24.799,48.576 24.468,48.307 ccw(c24.014,48.12) 24.201,48.574
N02082 on TOP "TOP104" (solid, pour order 228): 40.344,31.364 cw(c40.425,31.128) 40.506,31.364 ccw(c41.174,31.603) 40.806,30.997 40.425,30.553 40.044,30.997 ccw(c39.676,31.603) 40.344,31.364
N02082 on TOP "TOP103" (solid, pour order 227): 40.599,31.632 cw(c40.426,31.812) 40.303,31.595 ccw(c39.383,31.287) 39.852,32.136 40.298,32.653 40.762,32.136 ccw(c41.366,31.662) 40.599,31.632
N026301 on TOP "TOP102" (solid, pour order 226): 36.24,37.074 cw(c36.046,36.915) 36.256,36.779 ccw(c36.639,35.655) 35.587,36.206 34.763,36.837 35.587,37.476 ccw(c36.424,38.104) 36.24,37.074
N026301 on TOP "TOP101" (solid, pour order 225): 35.976,36.779 cw(c36.186,36.915) 35.992,37.074 ccw(c35.808,38.104) 36.645,37.476 37.469,36.837 36.645,36.206 ccw(c35.593,35.655) 35.976,36.779
N23263 on TOP "TOP99" (solid, pour order 223): 36.947,64.654 cw(c37.025,64.576) 37.103,64.654 ccw(c37.452,64.797) 37.308,64.449 37.025,64.138 36.742,64.449 ccw(c36.598,64.797) 36.947,64.654
N23263 on TOP "TOP98" (solid, pour order 222): 36.431,63.88 cw(c36.439,63.99) 36.361,64.068 ccw(c36.095,64.715) 36.742,64.449 37.051,64.174 36.811,63.851 ccw(c36.586,63.409) 36.431,63.88
N23263 on TOP "TOP97" (solid, pour order 221): 37.089,64.124 cw(c37.025,64.214) 36.961,64.124 ccw(c36.358,63.914) 36.644,64.485 37.025,64.893 37.406,64.485 ccw(c37.692,63.914) 37.089,64.124
N23267 on TOP "TOP96" (solid, pour order 220): 30.85,63.826 cw(c30.74,63.826) 30.74,63.716 ccw(c30.595,63.368) 30.45,63.716 30.431,64.135 30.85,64.116 ccw(c31.197,63.971) 30.85,63.826
N23267 on TOP "TOP95" (solid, pour order 219): 30.303,64.829 ccw(c31.033,65.129) 30.733,64.399 30.459,64.09 30.225,64.341 30.225,64.751
N23267 on TOP "TOP94" (solid, pour order 218): 30.273,64.242 cw(c30.225,64.341) 30.177,64.242 ccw(c29.744,64.045) 29.925,64.485 30.225,64.893 30.525,64.485 ccw(c30.706,64.045) 30.273,64.242
N23279 on TOP "TOP93" (solid, pour order 217): 33.9,63.491 33.626,63.765 33.612,64.119 34.025,64.091 ccw(c34.746,63.791) 34.025,63.491
N23279 on TOP "TOP92" (solid, pour order 216): 33.537,64.568 cw(c33.625,64.48) 33.713,64.568 ccw(c34.044,64.704) 33.908,64.374 33.625,64.06 33.342,64.374 ccw(c33.206,64.705) 33.537,64.568
N23279 on TOP "TOP91" (solid, pour order 215): 33.695,64.125 cw(c33.625,64.229) 33.555,64.125 ccw(c32.952,63.918) 33.244,64.485 33.625,64.897 34.006,64.485 ccw(c34.298,63.918) 33.695,64.125
N2368928 on TOP "TOP90" (solid, pour order 214): 35.34,64.124 cw(c35.276,64.214) 35.212,64.124 ccw(c34.608,63.913) 34.894,64.485 35.275,64.894 35.656,64.485 ccw(c35.943,63.914) 35.34,64.124
N36723 on TOP "TOP85" (solid, pour order 209): 19 vertices, not listed, extent 52.716,69.9 60.695,74.668
N36723 on TOP "TOP84" (solid, pour order 208): 52.039,70.838 cw(c51.951,70.926) 51.862,70.838 ccw(c51.532,70.703) 51.668,71.032 51.951,71.346 52.234,71.032 ccw(c52.369,70.703) 52.039,70.838
N36723 on TOP "TOP83" (solid, pour order 207): 54.81,69.697 cw(c54.704,69.59) 54.81,69.484 ccw(c54.933,69.183) 54.632,69.308 54.313,69.591 54.633,69.874 ccw(c54.934,69.998) 54.81,69.697
N36737 on TOP "TOP82" (solid, pour order 206): 45.25,50.145 45.343,50.145 45.355,50.133 45.361,50.133 46.62,48.874 46.62,44.427 46.313,44.12 45.385,44.12 45.375,44.13 45.155,44.13 44.862,44.424 44.862,44.866 44.905,44.873 ccw(c44.886,44.998) 44.941,44.884 ccw(c44.698,45.38) 45.25,45.38
N36741 on TOP "TOP81" (solid, pour order 205): 44.175,50.508 44.182,50.508 44.513,50.176 44.513,46.184 44.378,46.049 44.32,46.049 44.056,46.313 44.056,50.464 44.101,50.51 44.174,50.51
N36761 on TOP "TOP80" (solid, pour order 204): 42.31,47.575 cw(c42.399,47.64) 42.314,47.71 ccw(c42.15,48.322) 42.694,47.997 43.102,47.615 42.694,47.235 ccw(c42.084,46.933) 42.31,47.575
N36761 on TOP "TOP79" (solid, pour order 203): 42.017,47.704 cw(c41.928,47.64) 42.017,47.576 ccw(c42.226,46.973) 41.656,47.26 41.247,47.641 41.656,48.022 ccw(c42.228,48.308) 42.017,47.704
N36787 on TOP "TOP78" (solid, pour order 202): 54.735,44.925 60.04,44.925 60.44,44.525 60.44,41.221 60.14,40.921 56.585,40.921 56.073,40.408 55.777,40.408 55.27,40.915 55.27,40.921 54.434,40.921 54.134,41.221 54.134,44.324
N36795 on TOP "TOP77" (solid, pour order 201): 60.055,51.117 60.662,50.51 60.662,48.606 60.007,47.952 54.069,47.952 53.497,48.523 53.497,50.51 54.104,51.117
N36795 on TOP "TOP76" (solid, pour order 200): 52.223,50.489 cw(c52.312,50.578) 52.223,50.666 52.418,50.861 52.732,50.578 52.418,50.295 52.223,50.489
N36815 on TOP "TOP75" (solid, pour order 199): 58.675,39.404 cw(c58.675,39.529) 58.586,39.616 ccw(c58.458,39.919) 58.763,39.796 59.774,39.714 59.032,39.404 ccw(c58.854,38.977) 58.675,39.404
N36835 on TOP "TOP74" (solid, pour order 198): 43.036,50.182 cw(c43.101,50.093) 43.171,50.178 ccw(c43.783,50.339) 43.456,49.797 43.074,49.388 42.694,49.797 ccw(c42.391,50.409) 43.036,50.182
N36895 on TOP "TOP73" (solid, pour order 197): 41.617,61.432 cw(c41.501,61.478) 41.424,61.38 ccw(c40.496,61.044) 40.919,61.935 41.293,62.346 41.681,61.935 ccw(c42.272,61.605) 41.617,61.432
N3758319 on TOP "TOP72" (solid, pour order 196): 44.15,63.076 cw(c44.04,63.076) 44.04,62.966 ccw(c43.895,62.619) 43.75,62.966 43.731,63.385 44.15,63.366 ccw(c44.497,63.221) 44.15,63.076
N3758320 on TOP "TOP71" (solid, pour order 195): 44.125,61.851 cw(c44.015,61.851) 44.015,61.741 43.725,61.741 43.706,62.16 44.125,62.141 44.125,61.851
NFAULT on TOP "TOP70" (solid, pour order 194): 45.129,67.252 cw(c45.051,67.33) 44.973,67.252 ccw(c44.445,67.035) 44.662,67.563 44.941,67.669 45.161,67.669 45.44,67.563 ccw(c45.657,67.035) 45.129,67.252
NFAULT on TOP "TOP69" (solid, pour order 193): 39.051,53.055 cw(c39.161,53.055) 39.161,53.165 ccw(c39.306,53.513) 39.451,53.165 39.47,52.746 39.051,52.765 ccw(c38.703,52.91) 39.051,53.055
NFAULT on TOP "TOP68" (solid, pour order 192): 45.158,67.665 cw(c45.051,67.641) 45.158,67.617 ccw(c45.322,67.321) 45.006,67.441 44.598,67.641 45.006,67.842 ccw(c45.322,67.961) 45.158,67.665
NFAULT on TOP "TOP67" (solid, pour order 191): 45.584,67.577 cw(c45.673,67.641) 45.584,67.705 ccw(c45.373,68.308) 45.944,68.022 46.353,67.641 45.944,67.26 ccw(c45.373,66.974) 45.584,67.577
NRESET on TOP "TOP66" (solid, pour order 190): 28.086,45.107 28.086,44.939 27.92,44.939 27.912,44.93 27.912,44.772 27.914,44.769 27.914,44.714 27.901,44.701 27.087,44.701 26.836,44.952 26.836,45.061 26.89,45.115 28.077,45.115
NRESET on TOP "TOP65" (solid, pour order 189): 27.688,44.938 cw(c27.766,45.015) 27.688,45.093 27.893,45.298 28.203,45.015 27.893,44.733 27.688,44.938
NRESET on TOP "TOP64" (solid, pour order 188): 28.914,45.187 28.459,44.733 28.15,45.006 28.426,45.265 28.836,45.265
PDELAY on TOP "TOP61" (solid, pour order 185): 32.565,55.641 cw(c32.565,55.531) 32.675,55.531 32.675,55.291 32.306,55.272 32.325,55.641 32.565,55.641
PGND on TOP "TOP60" (solid, pour order 184): 56.251,62.889 56.251,61.486 55.418,60.652 52.798,60.652 52.307,61.144 52.307,64.661 52.101,64.661 52.101,64.82 cw(c53.096,64.82) 53.071,65.815 55.613,65.815 55.805,66.007 56.057,66.007 cw(c56.057,65.602) 56.365,65.865 57.314,64.916 57.314,63.952
PGND on TOP "TOP59" (solid, pour order 183): 54.827,36.637 54.829,36.639 55.859,36.639 56.106,36.392 57.025,36.392 57.404,36.013 57.404,32.141 56.695,31.432 54.592,31.432 52.713,33.311 52.713,35.724 53.628,36.639 54.807,36.639 54.808,36.637
PGND on TOP "TOP58" (solid, pour order 182): 43.2,59.491 47.625,59.491 47.625,55.141 43.2,55.141
PGND on TOP "TOP57" (solid, pour order 181): 40.924,45.706 cw(c41.101,45.529) 41.336,45.612 41.392,45.455 41.038,45.205 40.767,45.549 40.924,45.706
PGND on TOP "TOP56" (solid, pour order 180): 41.336,44.919 cw(c41.1,45.003) 40.923,44.827 40.767,44.983 41.038,45.327 41.391,45.076 41.336,44.919
PGND on TOP "TOP55" (solid, pour order 179): 41.019,45.089 cw(c41.1,44.853) 41.182,45.089 41.481,44.722 41.1,44.278 40.719,44.722 41.019,45.089
PGND on TOP "TOP54" (solid, pour order 178): 41.182,45.317 cw(c41.101,45.554) 41.019,45.317 40.719,45.685 41.1,46.129 41.481,45.685 41.182,45.317
PGND on TOP "TOP53" (solid, pour order 177): 27 vertices, not listed, extent 41.735,29.071 44.742,32.581
PGND on TOP "TOP52" (solid, pour order 176): 32 vertices, not listed, extent 52.518,54.48 57.221,58.958
PGND on TOP "TOP51" (solid, pour order 175): 53.06,37.072 cw(c52.954,36.966) 53.06,36.86 52.883,36.683 52.563,36.966 52.883,37.249 53.06,37.072
PGND on TOP "TOP50" (solid, pour order 174): 50.727,42.546 cw(c50.851,42.53) 50.939,42.618 51.284,42.273 51.009,41.96 50.683,42.201 50.727,42.546
PGND on TOP "TOP49" (solid, pour order 173): 53.21,53.971 cw(c53.104,53.865) 53.21,53.759 53.032,53.583 52.713,53.866 53.033,54.149 53.21,53.971
PGND on TOP "TOP48" (solid, pour order 172): 50.05,69.541 cw(c50.05,69.666) 49.925,69.666 49.925,69.941 50.347,69.963 50.325,69.541 50.05,69.541
PGND on TOP "TOP47" (solid, pour order 171): 54.91,66.546 cw(c54.804,66.44) 54.844,66.296 54.566,66.22 54.314,66.549 54.633,66.824 54.91,66.546
REGOUT1 on TOP "TOP45" (solid, pour order 169): 34.744,50.164 cw(c34.826,50.09) 34.892,50.178 ccw(c35.614,50.438) 35.281,49.747 34.903,49.339 34.519,49.747 ccw(c34.117,50.233) 34.744,50.164
RXD on TOP "TOP44" (solid, pour order 168): 23.951,47.105 cw(c24.061,47.105) 24.061,47.215 24.251,47.215 24.27,46.896 23.951,46.915 23.951,47.105
SB+ on TOP "TOP43" (solid, pour order 167): 33.976,38.24 33.251,37.515 33.251,36.065 33.026,35.84 32.026,35.84 31.801,36.065 31.801,39.74 32.151,40.09 32.251,40.19 33.976,40.19
SCLK on TOP "TOP41" (solid, pour order 165): 23.675,45.291 cw(c23.775,45.291) 23.775,45.391 24.075,45.391 24.093,44.973 23.675,44.991 23.675,45.291
SCLK on TOP "TOP40" (solid, pour order 164): 30.65,56.481 cw(c30.76,56.481) 30.76,56.591 31.05,56.591 31.069,56.172 30.65,56.191 30.65,56.481
SDO on TOP "TOP37" (solid, pour order 161): 23.86,57.841 cw(c23.86,57.951) 23.75,57.951 23.75,58.141 24.069,58.16 24.05,57.841 23.86,57.841
SDO on TOP "TOP36" (solid, pour order 160): 23.831,58.054 cw(c23.856,57.947) 23.966,57.947 23.856,57.01 23.46,57.368 23.094,57.772 23.831,58.054
SDO on TOP "TOP35" (solid, pour order 159): 31.313,57.012 cw(c31.391,57.09) 31.374,57.199 31.729,57.254 31.978,56.933 31.668,56.657 31.313,57.012
SDO on TOP "TOP34" (solid, pour order 158): 44.176,64.275 cw(c44.066,64.275) 44.066,64.165 43.776,64.165 43.756,64.585 44.176,64.565 44.176,64.275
